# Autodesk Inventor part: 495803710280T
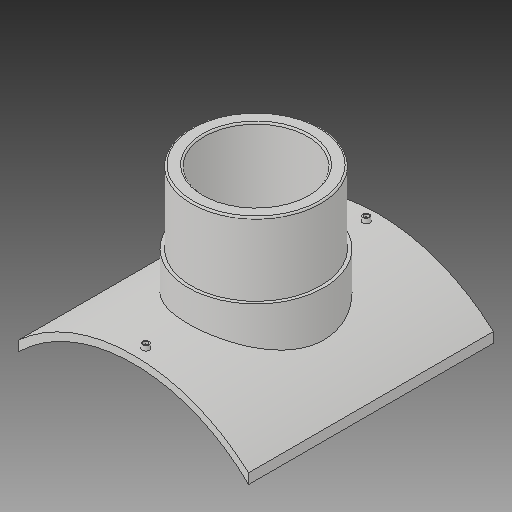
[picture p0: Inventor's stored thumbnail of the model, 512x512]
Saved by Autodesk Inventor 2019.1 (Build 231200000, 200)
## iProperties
Created: 2017-10
Part Number: 495803710280T
Material: Generic
Description: PLASSON BRANCH SADDLE  710x280
Document SubType Name: Modeling
Designer: KIM
Mass: 2754.05 g
Surface Area: 3037.44 cm^2
Volume: 2754.05 cm^3
Density: 1 g/cm^3
Appearance: Default
Author: KIM
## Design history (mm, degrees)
derived "495803.ipt"
feature "Solid1::495803.ipt"
tag "TaggingFeature1"
body "Solid1"
other parameters: "d1" = 16, "d2" = 498, "d4" = 0, "d12" = 380.6, "d13" = 14, "d14" = 238.5, "d16" = 5 deg, "d18" = 4, "d19" = 14, "d20" = 0, "d21" = 3, "d22" = 0, "d23" = 596, "d24" = 294, "d25" = 16, "d26" = 224, "d28" = 0, "d29" = 9.6, "d31" = 0, "d32" = 112.5, "d33" = 0, "d34" = 7.1, "d37" = 157.5, "d38" = 0, "d39" = 3.55, "B_" = 498, "H_" = 225, "x_" = 16, "D_" = 16
